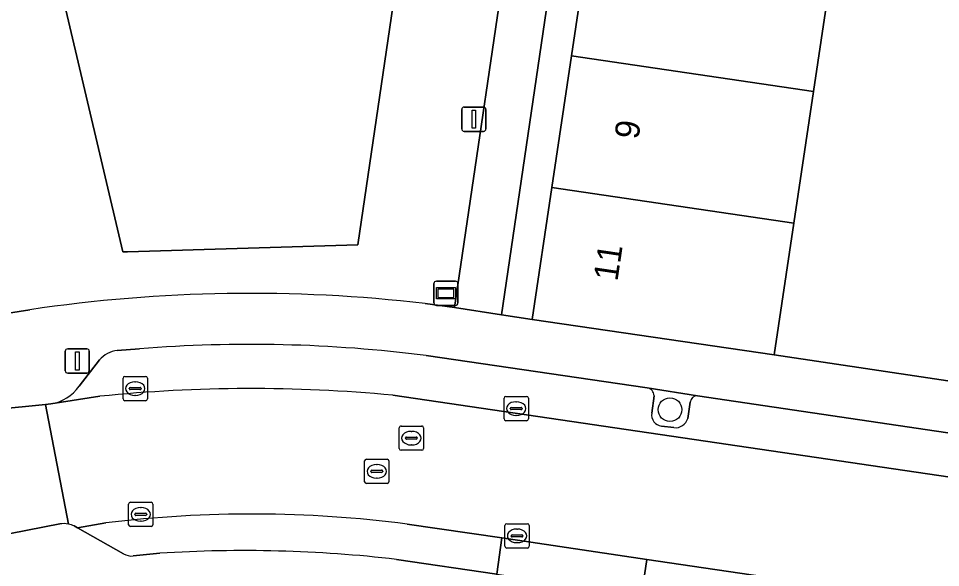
# Model space of a CAD drawing. Extents: x 164148 to 165261, y 382513 to 383432.
# Drawn here: x 164294.28 to 164332.23, y 383301.79 to 383324.4 of the extents above; entities that cross this region are included whole.
import ezdxf

# ---------------------------------------------------------------- set-up
doc = ezdxf.new("R2010")
doc.units = 0
for name, color, linetype in [('IMGEO_Boom', 7, 'Continuous'), ('IMGEO_Erf', 7, 'Continuous'), ('IMGEO_Groenvoorziening', 7, 'Continuous'), ('IMGEO_Kolk', 7, 'Continuous'), ('IMGEO_Lichtmast', 7, 'Continuous'), ('IMGEO_Muur', 7, 'Continuous'), ('IMGEO_Pand', 7, 'Continuous'), ('IMGEO_Pand_nummerreeks', 7, 'Continuous'), ('IMGEO_Parkeervlak_open', 7, 'Continuous'), ('IMGEO_Rijbaan_lokaal_open', 7, 'Continuous'), ('IMGEO_Rioolput', 7, 'Continuous'), ('IMGEO_Straatnaambord', 7, 'Continuous'), ('IMGEO_Voetpad_open', 7, 'Continuous')]:
    doc.layers.add(name, color=color, linetype=linetype)

msp = doc.modelspace()

# ---------------------------------------------------------------- linework, layer by layer
at = {"layer": 'IMGEO_Boom'}
msp.add_circle((164321.094, 383308.291), 0.489, dxfattribs=at)
at = {"layer": 'IMGEO_Erf'}
msp.add_lwpolyline([(164318.947, 383344.792), (164314.155, 383312.192), (164315.417, 383312.007), (164316.226, 383317.439), (164317.036, 383322.87), (164317.845, 383328.301), (164318.654, 383333.732), (164319.463, 383339.163), (164320.273, 383344.594)], close=True, dxfattribs=at)
msp.add_lwpolyline([(164340.573, 383341.556), (164330.233, 383343.112), (164329.426, 383337.691), (164328.618, 383332.26), (164327.81, 383326.829), (164327.001, 383321.398), (164326.193, 383315.967), (164325.386, 383310.546), (164335.741, 383308.998)], dxfattribs=at)
at = {"layer": 'IMGEO_Groenvoorziening'}
for points in [[(164311.017, 383312.663), (164312.229, 383312.499), (164317.302, 383347.003), (164319.267, 383346.752), (164361.497, 383340.519), (164364.451, 383340.089), (164366.01, 383350.778), (164366.226, 383351.016), (164366.184, 383351.206), (164367.887, 383363.095)], [(164288.608, 383344.616), (164288.559, 383340.258), (164288.545, 383334.327), (164288.542, 383328.749), (164288.548, 383326.209), (164288.764, 383320.886), (164289.531, 383316.138), (164290.723, 383316.331), (164291.092, 383314.18), (164291.484, 383311.894), (164294.748, 383312.409)], [(164322.228, 383308.865), (164320.159, 383309.193)], [(164320.444, 383308.866), (164320.341, 383308.147)], [(164321.822, 383307.932), (164321.93, 383308.606)], [(164320.745, 383307.613), (164321.255, 383307.553)]]:
    msp.add_lwpolyline(points, dxfattribs=at)
for points in [[(164313.822, 383353.004), (164289.902, 383344.437), (164295.387, 383328.333), (164298.574, 383314.789), (164298.768, 383314.794), (164308.247, 383315.073)], [(164308.247, 383315.073), (164298.768, 383314.794), (164298.574, 383314.789), (164295.387, 383328.333), (164289.902, 383344.437), (164313.822, 383353.004)]]:
    msp.add_lwpolyline(points, close=True, dxfattribs=at)
for centre, radius, start, end in [((164303.842, 383251.078), 62.001, 83.35464, 98.43428), ((164320.089, 383308.844), 0.356, 3.5346, 78.6136), ((164322.21, 383308.585), 0.281, 86.2847, 175.7049), ((164320.809, 383308.081), 0.472, 171.9573, 262.2617), ((164321.325, 383308.061), 0.513, 262.1225, 345.3974)]:
    msp.add_arc(centre, radius, start, end, dxfattribs=at)
at = {"layer": 'IMGEO_Kolk'}
for p, q in [((164298.659, 383309.659), (164299.511, 383309.659)), ((164298.584, 383308.733), (164298.584, 383309.585)), ((164299.072, 383309.439), (164299.097, 383309.439)), ((164299.585, 383309.585), (164299.585, 383308.733)), ((164298.843, 383309.153), (164298.843, 383309.165)), ((164299.281, 383309.116), (164298.883, 383309.116)), ((164298.886, 383309.202), (164299.284, 383309.202)), ((164299.095, 383308.879), (164299.07, 383308.879)), ((164299.327, 383309.165), (164299.327, 383309.153)), ((164299.511, 383308.659), (164298.659, 383308.659)), ((164314.264, 383307.91), (164314.264, 383308.762)), ((164314.339, 383308.836), (164315.191, 383308.836)), ((164314.752, 383308.616), (164314.777, 383308.616)), ((164315.265, 383308.762), (164315.265, 383307.91)), ((164314.523, 383308.33), (164314.523, 383308.342)), ((164314.961, 383308.293), (164314.563, 383308.293)), ((164314.566, 383308.379), (164314.964, 383308.379)), ((164315.007, 383308.342), (164315.007, 383308.33)), ((164315.191, 383307.836), (164314.339, 383307.836)), ((164314.775, 383308.056), (164314.75, 383308.056)), ((164298.815, 383303.553), (164298.815, 383304.405)), ((164298.89, 383304.479), (164299.742, 383304.479)), ((164299.816, 383304.405), (164299.816, 383303.553)), ((164299.074, 383303.973), (164299.074, 383303.985)), ((164299.512, 383303.936), (164299.114, 383303.936)), ((164299.117, 383304.022), (164299.515, 383304.022)), ((164299.303, 383304.259), (164299.328, 383304.259)), ((164299.558, 383303.985), (164299.558, 383303.973)), ((164299.326, 383303.699), (164299.301, 383303.699)), ((164314.375, 383303.593), (164315.227, 383303.593)), ((164299.742, 383303.479), (164298.89, 383303.479)), ((164314.3, 383302.667), (164314.3, 383303.519)), ((164314.788, 383303.373), (164314.813, 383303.373)), ((164315.301, 383303.519), (164315.301, 383302.667)), ((164314.559, 383303.087), (164314.559, 383303.099)), ((164314.997, 383303.05), (164314.599, 383303.05)), ((164314.602, 383303.136), (164315, 383303.136)), ((164314.811, 383302.813), (164314.786, 383302.813)), ((164315.043, 383303.099), (164315.043, 383303.087)), ((164315.227, 383302.593), (164314.375, 383302.593))]:
    msp.add_line(p, q, dxfattribs=at)
for points in [[(164298.659, 383309.659), (164299.511, 383309.659)], [(164298.584, 383308.733), (164298.584, 383309.585)], [(164299.585, 383309.585), (164299.585, 383308.733)], [(164299.511, 383308.659), (164298.659, 383308.659)], [(164314.264, 383307.91), (164314.264, 383308.762)], [(164314.339, 383308.836), (164315.191, 383308.836)], [(164315.265, 383308.762), (164315.265, 383307.91)], [(164315.191, 383307.836), (164314.339, 383307.836)], [(164298.815, 383303.553), (164298.815, 383304.405)], [(164298.89, 383304.479), (164299.742, 383304.479)], [(164299.816, 383304.405), (164299.816, 383303.553)], [(164314.375, 383303.593), (164315.227, 383303.593)], [(164299.742, 383303.479), (164298.89, 383303.479)], [(164314.3, 383302.667), (164314.3, 383303.519)], [(164315.301, 383303.519), (164315.301, 383302.667)], [(164315.227, 383302.593), (164314.375, 383302.593)]]:
    msp.add_lwpolyline(points, dxfattribs=at)
for centre, radius, start, end in [((164298.661, 383309.583), 0.0765, 91.552, 178.448), ((164298.661, 383309.583), 0.0765, 91.552, 178.448), ((164299.509, 383309.583), 0.0765, 1.552, 88.448), ((164299.509, 383309.583), 0.0765, 1.552, 88.448), ((164298.883, 383309.162), 0.0403, 85.8775, 175.7526), ((164298.88, 383309.152), 0.0366, 178.938, 274.7102), ((164299.284, 383309.159), 0.043, 264.8664, 352.4533), ((164299.288, 383309.164), 0.0386, 1.7309, 96.639), ((164298.661, 383308.735), 0.0765, 181.552, 268.448), ((164298.661, 383308.735), 0.0765, 181.552, 268.448), ((164299.509, 383308.735), 0.0765, 271.552, 358.448), ((164299.509, 383308.735), 0.0765, 271.552, 358.448), ((164314.341, 383308.76), 0.0765, 91.552, 178.448), ((164314.341, 383308.76), 0.0765, 91.552, 178.448), ((164315.189, 383308.76), 0.0765, 1.552, 88.448), ((164315.189, 383308.76), 0.0765, 1.552, 88.448), ((164314.563, 383308.339), 0.0403, 85.8775, 175.7526), ((164314.56, 383308.329), 0.0366, 178.938, 274.7102), ((164314.964, 383308.336), 0.043, 264.8664, 352.4533), ((164314.968, 383308.341), 0.0386, 1.7309, 96.639), ((164314.341, 383307.912), 0.0765, 181.552, 268.448), ((164314.341, 383307.912), 0.0765, 181.552, 268.448), ((164315.189, 383307.912), 0.0765, 271.552, 358.448), ((164315.189, 383307.912), 0.0765, 271.552, 358.448), ((164298.892, 383304.403), 0.0765, 91.552, 178.448), ((164298.892, 383304.403), 0.0765, 91.552, 178.448), ((164299.74, 383304.403), 0.0765, 1.552, 88.448), ((164299.74, 383304.403), 0.0765, 1.552, 88.448), ((164299.114, 383303.982), 0.0403, 85.8775, 175.7526), ((164299.111, 383303.972), 0.0366, 178.938, 274.7102), ((164299.515, 383303.979), 0.043, 264.8664, 352.4533), ((164299.519, 383303.984), 0.0386, 1.7309, 96.639), ((164314.377, 383303.517), 0.0765, 91.552, 178.448), ((164314.377, 383303.517), 0.0765, 91.552, 178.448), ((164315.225, 383303.517), 0.0765, 1.552, 88.448), ((164315.225, 383303.517), 0.0765, 1.552, 88.448), ((164298.892, 383303.555), 0.0765, 181.552, 268.448), ((164298.892, 383303.555), 0.0765, 181.552, 268.448), ((164299.74, 383303.555), 0.0765, 271.552, 358.448), ((164299.74, 383303.555), 0.0765, 271.552, 358.448), ((164314.599, 383303.096), 0.0403, 85.8775, 175.7526), ((164314.596, 383303.086), 0.0366, 178.938, 274.7102), ((164315, 383303.093), 0.043, 264.8664, 352.4533), ((164315.004, 383303.098), 0.0386, 1.7309, 96.639), ((164314.377, 383302.669), 0.0765, 181.552, 268.448), ((164314.377, 383302.669), 0.0765, 181.552, 268.448), ((164315.225, 383302.669), 0.0765, 271.552, 358.448), ((164315.225, 383302.669), 0.0765, 271.552, 358.448)]:
    msp.add_arc(centre, radius, start, end, dxfattribs=at)
for centre, major_axis, ratio, start_param, end_param in [((164299.071, 383309.159), (-0.387, 0.002), 0.722429, 4.712389, 7.853982), ((164299.096, 383309.159), (-0.39, 0.002), 0.717154, 1.570796, 4.712389), ((164314.751, 383308.336), (-0.387, 0.002), 0.722429, 4.712389, 7.853982), ((164314.776, 383308.336), (-0.39, 0.002), 0.717154, 1.570796, 4.712389), ((164299.302, 383303.979), (-0.387, 0.002), 0.722429, 4.712389, 7.853982), ((164299.327, 383303.979), (-0.39, 0.002), 0.717154, 1.570796, 4.712389), ((164314.787, 383303.093), (-0.387, 0.002), 0.722429, 4.712389, 7.853982), ((164314.812, 383303.093), (-0.39, 0.002), 0.717154, 1.570796, 4.712389)]:
    msp.add_ellipse(centre, major_axis=major_axis, ratio=ratio, start_param=start_param, end_param=end_param, dxfattribs=at)
at = {"layer": 'IMGEO_Lichtmast'}
for p, q in [((164312.526, 383319.853), (164312.526, 383320.653)), ((164312.526, 383320.653), (164312.526, 383319.853)), ((164312.626, 383320.753), (164313.416, 383320.753)), ((164313.416, 383320.753), (164312.626, 383320.753)), ((164313.516, 383320.653), (164313.516, 383319.853)), ((164313.516, 383319.853), (164313.516, 383320.653)), ((164313.416, 383319.753), (164312.626, 383319.753)), ((164312.626, 383319.753), (164313.416, 383319.753)), ((164296.307, 383310.796), (164297.097, 383310.796)), ((164297.097, 383310.796), (164296.307, 383310.796)), ((164296.207, 383309.896), (164296.207, 383310.696)), ((164296.207, 383310.696), (164296.207, 383309.896)), ((164297.197, 383310.696), (164297.197, 383309.896)), ((164297.197, 383309.896), (164297.197, 383310.696)), ((164297.097, 383309.796), (164296.307, 383309.796)), ((164296.307, 383309.796), (164297.097, 383309.796))]:
    msp.add_line(p, q, dxfattribs=at)
for points in [[(164312.946, 383320.628), (164313.096, 383320.628), (164313.096, 383319.878), (164312.946, 383319.878), (164312.946, 383320.628)], [(164296.627, 383310.671), (164296.777, 383310.671), (164296.777, 383309.921), (164296.627, 383309.921), (164296.627, 383310.671)]]:
    msp.add_lwpolyline(points, dxfattribs=at)
for centre, start, end in [((164312.626, 383320.653), 90, 180), ((164312.626, 383320.653), 90, 180), ((164313.416, 383320.653), 0, 90), ((164313.416, 383320.653), 360, 90), ((164312.626, 383319.853), 180, 270), ((164312.626, 383319.853), 180, 270), ((164313.416, 383319.853), 270, 0), ((164313.416, 383319.853), 270, 0), ((164296.307, 383310.696), 90, 180), ((164296.307, 383310.696), 90, 180), ((164297.097, 383310.696), 0, 90), ((164297.097, 383310.696), 360, 90), ((164296.307, 383309.896), 180, 270), ((164296.307, 383309.896), 180, 270), ((164297.097, 383309.896), 270, 0), ((164297.097, 383309.896), 270, 0)]:
    msp.add_arc(centre, 0.1, start, end, dxfattribs=at)
at = {"layer": 'IMGEO_Muur'}
msp.add_lwpolyline([(164335.741, 383308.998), (164325.386, 383310.546)], dxfattribs=at)
at = {"layer": 'IMGEO_Pand'}
for points in [[(164317.036, 383322.87), (164327.001, 383321.398), (164327.81, 383326.829), (164317.845, 383328.301)], [(164317.036, 383322.87), (164316.226, 383317.439), (164326.193, 383315.967), (164327.001, 383321.398)], [(164316.226, 383317.439), (164315.417, 383312.007), (164325.386, 383310.546), (164326.193, 383315.967)]]:
    msp.add_lwpolyline(points, close=True, dxfattribs=at)
at = {"layer": 'IMGEO_Parkeervlak_open'}
for points in [[(164299.261, 383310.8), (164298.346, 383310.725)], [(164320.159, 383309.193), (164311.06, 383310.519)], [(164297.615, 383310.34), (164296.778, 383309.253)], [(164309.687, 383308.887), (164354.167, 383302.338), (164354.649, 383302.259)], [(164295.617, 383308.525), (164297.635, 383308.843)], [(164320.341, 383308.147), (164320.444, 383308.866)], [(164321.93, 383308.606), (164321.822, 383307.932)], [(164345.054, 383305.487), (164322.228, 383308.865)], [(164321.255, 383307.553), (164320.745, 383307.613)], [(164297.881, 383303.624), (164296.717, 383303.419), (164298.606, 383302.356)], [(164309.843, 383302.124), (164313.968, 383301.521), (164314.168, 383303.013), (164310.282, 383303.577)], [(164298.998, 383302.267), (164300.098, 383302.376)]]:
    msp.add_lwpolyline(points, dxfattribs=at)
msp.add_lwpolyline([(164320.144, 383302.126), (164319.926, 383300.65), (164330.829, 383299.025), (164331.054, 383300.519)], close=True, dxfattribs=at)
for centre, radius, start, end in [((164303.799, 383253.475), 57.505, 82.74563, 94.52583), ((164298.46, 383309.622), 1.108, 95.8936, 139.6557), ((164295.297, 383310.326), 1.829, 280.0892, 324.09), ((164303.886, 383247.256), 61.904, 84.62285, 95.7955), ((164320.089, 383308.844), 0.356, 3.5346, 78.6136), ((164322.21, 383308.585), 0.281, 86.2847, 175.7049), ((164320.809, 383308.081), 0.472, 171.9573, 262.2617), ((164321.325, 383308.061), 0.513, 262.1225, 345.3974), ((164303.897, 383254.821), 49.173, 82.5387, 97.027), ((164303.571, 383248.114), 54.373, 83.3757, 93.6617), ((164298.927, 383302.861), 0.598, 237.586, 276.8308)]:
    msp.add_arc(centre, radius, start, end, dxfattribs=at)
at = {"layer": 'IMGEO_Rijbaan_lokaal_open'}
for points in [[(164310.282, 383303.577), (164314.168, 383303.013), (164320.144, 383302.126), (164331.054, 383300.519), (164342.533, 383298.815), (164351.856, 383297.431), (164353.437, 383297.172), (164354.167, 383302.338), (164309.687, 383308.887)], [(164296.338, 383303.578), (164295.396, 383308.499), (164293.314, 383308.3), (164293.054, 383308.275)], [(164297.635, 383308.843), (164295.617, 383308.525), (164295.396, 383308.499), (164296.338, 383303.578)], [(164292.986, 383302.941), (164293.428, 383303.084), (164293.442, 383303.088), (164293.947, 383303.187), (164295.98, 383303.584)], [(164296.572, 383303.5), (164296.717, 383303.419), (164297.881, 383303.624)]]:
    msp.add_lwpolyline(points, dxfattribs=at)
for centre, radius, start, end in [((164303.886, 383247.256), 61.904, 84.62285, 95.7955), ((164303.897, 383254.821), 49.173, 82.5387, 97.027), ((164296.143, 383302.626), 0.972, 78.4233, 99.6563), ((164296.175, 383302.698), 0.895, 63.6444, 79.4857)]:
    msp.add_arc(centre, radius, start, end, dxfattribs=at)
at = {"layer": 'IMGEO_Rioolput'}
for p, q in [((164309.951, 383306.692), (164309.951, 383307.544)), ((164310.026, 383307.618), (164310.878, 383307.618)), ((164310.439, 383307.398), (164310.464, 383307.398)), ((164310.952, 383307.544), (164310.952, 383306.692)), ((164310.21, 383307.112), (164310.21, 383307.124)), ((164310.648, 383307.075), (164310.25, 383307.075)), ((164310.253, 383307.161), (164310.651, 383307.161)), ((164310.694, 383307.124), (164310.694, 383307.112)), ((164310.878, 383306.618), (164310.026, 383306.618)), ((164310.462, 383306.838), (164310.437, 383306.838)), ((164308.602, 383306.251), (164309.454, 383306.251)), ((164308.527, 383305.325), (164308.527, 383306.177)), ((164309.015, 383306.031), (164309.04, 383306.031)), ((164309.528, 383306.177), (164309.528, 383305.325)), ((164308.786, 383305.745), (164308.786, 383305.757)), ((164309.224, 383305.708), (164308.826, 383305.708)), ((164308.829, 383305.794), (164309.227, 383305.794)), ((164309.038, 383305.471), (164309.013, 383305.471)), ((164309.27, 383305.757), (164309.27, 383305.745)), ((164309.454, 383305.251), (164308.602, 383305.251))]:
    msp.add_line(p, q, dxfattribs=at)
for points in [[(164309.951, 383306.692), (164309.951, 383307.544)], [(164310.026, 383307.618), (164310.878, 383307.618)], [(164310.952, 383307.544), (164310.952, 383306.692)], [(164310.878, 383306.618), (164310.026, 383306.618)], [(164308.602, 383306.251), (164309.454, 383306.251)], [(164308.527, 383305.325), (164308.527, 383306.177)], [(164309.528, 383306.177), (164309.528, 383305.325)], [(164309.454, 383305.251), (164308.602, 383305.251)]]:
    msp.add_lwpolyline(points, dxfattribs=at)
for centre, radius, start, end in [((164310.028, 383307.542), 0.0765, 91.552, 178.448), ((164310.028, 383307.542), 0.0765, 91.552, 178.448), ((164310.876, 383307.542), 0.0765, 1.552, 88.448), ((164310.876, 383307.542), 0.0765, 1.552, 88.448), ((164310.25, 383307.121), 0.0403, 85.8775, 175.7526), ((164310.247, 383307.111), 0.0366, 178.938, 274.7102), ((164310.651, 383307.118), 0.043, 264.8664, 352.4533), ((164310.655, 383307.123), 0.0386, 1.7309, 96.639), ((164310.028, 383306.694), 0.0765, 181.552, 268.448), ((164310.028, 383306.694), 0.0765, 181.552, 268.448), ((164310.876, 383306.694), 0.0765, 271.552, 358.448), ((164310.876, 383306.694), 0.0765, 271.552, 358.448), ((164308.604, 383306.175), 0.0765, 91.552, 178.448), ((164308.604, 383306.175), 0.0765, 91.552, 178.448), ((164309.452, 383306.175), 0.0765, 1.552, 88.448), ((164309.452, 383306.175), 0.0765, 1.552, 88.448), ((164308.826, 383305.754), 0.0403, 85.8775, 175.7526), ((164308.823, 383305.744), 0.0366, 178.938, 274.7102), ((164309.227, 383305.751), 0.043, 264.8664, 352.4533), ((164309.231, 383305.756), 0.0386, 1.7309, 96.639), ((164308.604, 383305.327), 0.0765, 181.552, 268.448), ((164308.604, 383305.327), 0.0765, 181.552, 268.448), ((164309.452, 383305.327), 0.0765, 271.552, 358.448), ((164309.452, 383305.327), 0.0765, 271.552, 358.448)]:
    msp.add_arc(centre, radius, start, end, dxfattribs=at)
for centre, major_axis, ratio, start_param, end_param in [((164310.438, 383307.118), (-0.387, 0.002), 0.722429, 4.712389, 7.853982), ((164310.463, 383307.118), (-0.39, 0.002), 0.717154, 1.570796, 4.712389), ((164309.014, 383305.751), (-0.387, 0.002), 0.722429, 4.712389, 7.853982), ((164309.039, 383305.751), (-0.39, 0.002), 0.717154, 1.570796, 4.712389)]:
    msp.add_ellipse(centre, major_axis=major_axis, ratio=ratio, start_param=start_param, end_param=end_param, dxfattribs=at)
at = {"layer": 'IMGEO_Straatnaambord'}
for p, q in [((164311.378, 383312.684), (164311.378, 383313.484)), ((164311.378, 383313.484), (164311.378, 383312.684)), ((164311.478, 383313.584), (164312.268, 383313.584)), ((164312.268, 383313.584), (164311.478, 383313.584)), ((164312.368, 383313.484), (164312.368, 383312.684)), ((164312.368, 383312.684), (164312.368, 383313.484)), ((164312.268, 383312.584), (164311.478, 383312.584)), ((164311.478, 383312.584), (164312.268, 383312.584))]:
    msp.add_line(p, q, dxfattribs=at)
for points in [[(164311.479, 383313.316), (164312.267, 383313.316), (164312.267, 383312.852), (164311.479, 383312.852), (164311.479, 383313.316)], [(164311.544, 383313.251), (164311.544, 383312.917), (164312.202, 383312.917), (164312.202, 383313.251), (164311.544, 383313.251)]]:
    msp.add_lwpolyline(points, dxfattribs=at)
for centre, start, end in [((164311.478, 383313.484), 90, 180), ((164311.478, 383313.484), 90, 180), ((164312.268, 383313.484), 0, 90), ((164312.268, 383313.484), 360, 90), ((164311.478, 383312.684), 180, 270), ((164311.478, 383312.684), 180, 270), ((164312.268, 383312.684), 270, 0), ((164312.268, 383312.684), 270, 0)]:
    msp.add_arc(centre, 0.1, start, end, dxfattribs=at)
at = {"layer": 'IMGEO_Voetpad_open'}
for points in [[(164318.947, 383344.792), (164320.273, 383344.594), (164330.233, 383343.112), (164340.573, 383341.556), (164342.573, 383341.273), (164352.927, 383339.746), (164362.9, 383338.272), (164364.159, 383338.027), (164364.451, 383340.089), (164361.497, 383340.519), (164319.267, 383346.752), (164317.302, 383347.003), (164312.229, 383312.499), (164314.155, 383312.192)], [(164320.144, 383302.126), (164314.168, 383303.013), (164313.968, 383301.521), (164319.926, 383300.65)]]:
    msp.add_lwpolyline(points, close=True, dxfattribs=at)
for points in [[(164363.558, 383307.617), (164361.663, 383307.919), (164362.259, 383311.969), (164362.433, 383312.01), (164365.628, 383333.748), (164365.787, 383333.983), (164365.568, 383334.108), (164366.096, 383337.628), (164364.159, 383338.027), (164359.341, 383305.521), (164358.085, 383305.692), (164348.112, 383307.166), (164337.719, 383308.717), (164335.741, 383308.998), (164325.386, 383310.546), (164315.417, 383312.007)], [(164315.417, 383312.007), (164314.155, 383312.192), (164312.229, 383312.499), (164311.017, 383312.663)], [(164294.748, 383312.409), (164291.484, 383311.894), (164292.112, 383308.24)], [(164298.346, 383310.725), (164299.261, 383310.8)], [(164311.06, 383310.519), (164320.159, 383309.193), (164322.228, 383308.865), (164345.054, 383305.487), (164347.045, 383305.191), (164352.02, 383304.48)], [(164296.778, 383309.253), (164297.615, 383310.34)], [(164293.054, 383308.275), (164293.314, 383308.3), (164295.396, 383308.499), (164295.617, 383308.525)], [(164295.98, 383303.584), (164293.947, 383303.187), (164293.442, 383303.088), (164293.428, 383303.084), (164292.986, 383302.941), (164293.518, 383299.778), (164298.86, 383300.649)], [(164298.606, 383302.356), (164296.717, 383303.419), (164296.572, 383303.5)], [(164300.098, 383302.376), (164298.998, 383302.267)], [(164352.979, 383295.744), (164342.299, 383297.318), (164342.238, 383296.879), (164330.761, 383298.586), (164330.829, 383299.025), (164319.926, 383300.65), (164319.873, 383300.209), (164313.912, 383301.085), (164313.968, 383301.521), (164309.843, 383302.124)]]:
    msp.add_lwpolyline(points, dxfattribs=at)
for centre, radius, start, end in [((164303.842, 383251.078), 62.001, 83.35464, 98.43428), ((164303.799, 383253.475), 57.505, 82.74563, 94.52583), ((164298.46, 383309.622), 1.108, 95.8936, 139.6557), ((164295.297, 383310.326), 1.829, 280.0892, 324.09), ((164296.143, 383302.626), 0.972, 78.4233, 99.6563), ((164296.175, 383302.698), 0.895, 63.6444, 79.4857), ((164303.571, 383248.114), 54.373, 83.3757, 93.6617), ((164298.927, 383302.861), 0.598, 237.586, 276.8308)]:
    msp.add_arc(centre, radius, start, end, dxfattribs=at)

# ---------------------------------------------------------------- texts
at = {"layer": 'IMGEO_Pand_nummerreeks'}
for s, p in [('9', (164319.792, 383319.394)), ('11', (164318.93, 383313.552))]:
    msp.add_text(s, height=1, rotation=81.6025, dxfattribs=at).set_placement(p)

doc.saveas('drawing.dxf')
